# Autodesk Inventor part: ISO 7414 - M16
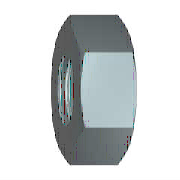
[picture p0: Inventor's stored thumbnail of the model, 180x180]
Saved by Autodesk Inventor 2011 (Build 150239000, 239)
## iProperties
IsCustomPart: 0
Created: 2009-02
Part Number: ISO 7414 - M16
Material: Steel
Description: Hexagon nuts for structural bolting with large width across flats, style1 - product B - property class 10
Document SubType Name: Modeling
Standard: ISO 7414
Designer: 904Chiaki
Standard Revision: First edition 1984-11-15
Standards Organization: ISO
Language: en-US
Size Designation: M16
Categories: <MemberInstance><Categories><Category DisplayName="Fasteners" InternalName="e4da775c-781d-43d5-af7c-5136215cf5a6" Mnemonic="FSTN"><Category DisplayName="Nuts" I
Density: 7.85 g/cm^3
Mass: 54.3321 g
Surface Area: 28.0487 cm^2
Volume: 6.92128 cm^3
Author: 904Chiaki
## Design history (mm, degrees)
body "Solid1"
workaxis "Work Axis1"
workplane "Work Plane1"
sketch "Sketch1"
  geometry: L1 (-15.588, 0)-(-7.794, 13.5); L2 (-7.794, 13.5)-(7.794, 13.5); L3 (7.794, 13.5)-(15.588, 0); L4 (15.588, 0)-(7.794, -13.5); L5 (7.794, -13.5)-(-7.794, -13.5); L6 (-7.794, -13.5)-(-15.588, 0); 2 further points
  constraints: 12 end point, 1 coincident, 1 horizontal, 11 other
  dimensions: "d0" = 31.17691 distance of L3.end L1.start (= 1.1547 x SW)
extrude "Body" new body sketch "Sketch1" distance "d1" = 14.8 (= KOH); taper "d2" = 0 deg
revolve "Chamfer1" stored, may be unused: angle "d7" = 90 deg
sketch "Sketch3"
  geometry: 4 further points
  constraints: 1 coincident, 1 other
hole "Thread" sketch "Sketch3" diameter "d25" = 13.835; stored, may be unused: countersink angle "d29" = 82 deg, drill point angle "d31" = 118 deg; dims "d26" = 6, "d27" = 4, "d28" = 2, "d30" = 8
chamfer "Chamfer2" distance "d8" = 1.08253 (= -0.5 x GD1 + 0.5 x NND); stored, may be unused: angle "d9" = 30 deg, second distance "d40" = 1.08253 (= -0.5 x GD1 + 0.5 x NND)
chamfer "Chamfer3" distance "d10" = 1.08253 (= -0.5 x GD1 + 0.5 x NND); stored, may be unused: angle "d11" = 30 deg, second distance "d41" = 1.08253 (= -0.5 x GD1 + 0.5 x NND)
sketch "Sketch2"
  geometry: L1 (0, 7.794)-(0, 15.588) reference; L2 (0, 15.588)-(14.8, 15.588) reference; L3 (14.8, 7.794)-(14.8, 15.588) reference; L4 (-2.96, 0)-(17.76, 0) reference; L5 (1.812, 15.588)-(0, 12.45); L6 (12.988, 15.588)-(14.8, 12.45)
  constraints: 4 end point, 4 point on line
  dimensions: "d3" = 30 deg angle of L1 L5 (= ANG1); "d4" = 30 deg angle of L3 L6 (= ANG2); "d5" = 24.9 diameter of L5.end L4 (= SW0); "d6" = 24.9 diameter of L6.end L4 (= SW01)
other parameters: "ANG1" = 30 deg [user parameter; used in 1 equation term], "ANG2" = 30 deg [user parameter; used in 1 equation term], "NND" = 16 [user parameter; used in 4 equation terms], "KOH" = 14.8 [user parameter; used in 1 equation term], "SW" = 27 [user parameter; used in 2 equation terms], "SW0" = 24.9 [user parameter; used in 2 equation terms], "SW01" = 24.9 (= SW0) [user parameter; used in 1 equation term], "GD1" = 13.83494 (computed from THREADDIA, PTC, TOA) [user parameter; used in 4 equation terms], "d13" = 0, "d14" = 0, "d39" = 0, "d42" = 0, "GUL" = 1.08253 (= 0.541266 x PTC) [user parameter], "TPU" = 5 (computed from PTC) [user parameter], "THREADDIA" = 16 [user parameter; used in 1 equation term], "TOA" = 30 deg [user parameter; used in 1 equation term], "PTC" = 2 [user parameter; used in 4 equation terms], "E0" = 31.185 (= 1.155 x SW) [user parameter], "GAL" = 1.08253 (= 0.541266 x PTC) [user parameter]
